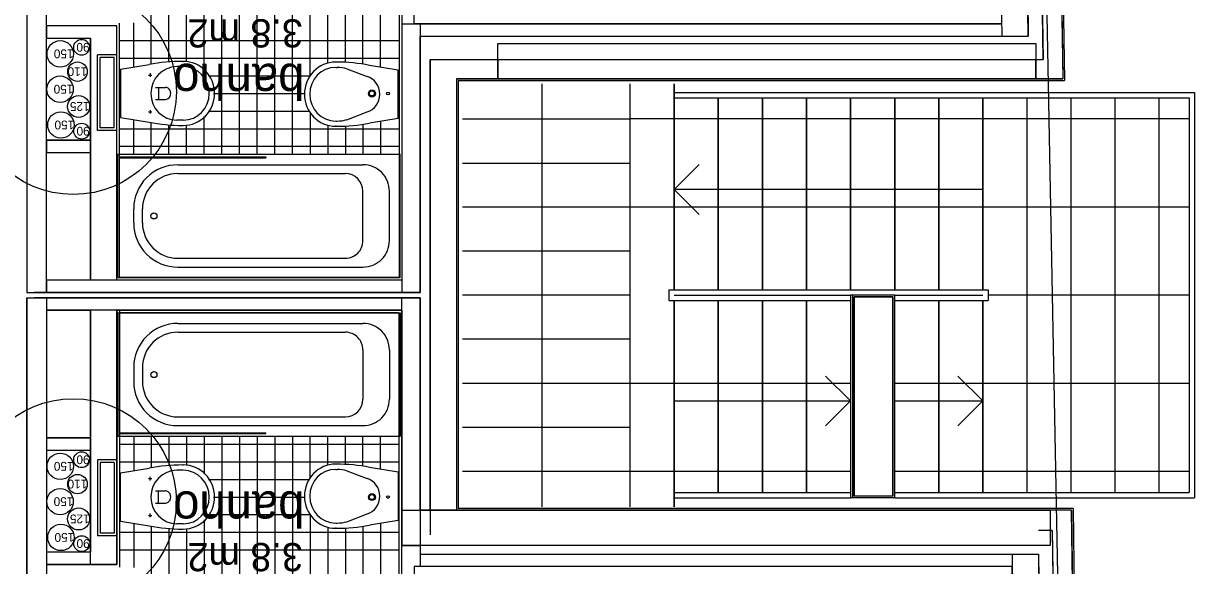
# Model space of a CAD drawing. Extents: x 1278 to 1356, y -253.7 to -224.
# Drawn here: x 1345.5 to 1352.14, y -240.96 to -237.88 of the extents above; entities that cross this region are included whole.
import ezdxf

# ---------------------------------------------------------------- set-up
doc = ezdxf.new("R2010")
doc.units = 0
for name, color, linetype in [('Level 1', 7, 'Continuous'), ('Level 10', 7, 'Continuous'), ('Level 11', 7, 'Continuous'), ('Level 2', 7, 'Continuous'), ('Level 36', 7, 'Continuous'), ('Level 41', 7, 'Continuous'), ('Level 60', 7, 'Continuous'), ('Level 65', 7, 'Continuous'), ('Level 66', 7, 'Continuous'), ('Level 67', 7, 'Continuous'), ('Level 69', 7, 'Continuous'), ('Level 70', 7, 'Continuous')]:
    doc.layers.add(name, color=color, linetype=linetype)

msp = doc.modelspace()

# ---------------------------------------------------------------- linework, layer by layer
at = {"layer": 'Level 1'}
for p, q in [((1351.0269, -236.264), (1351.0505, -237.954)), ((1351.1769, -236.2619), (1351.2005, -237.954)), ((1345.524, -236.7713), (1345.524, -239.409)), ((1347.6487, -237.829), (1347.6487, -239.409)), ((1347.6487, -237.884), (1351.0496, -237.884)), ((1347.719, -237.884), (1347.719, -237.829)), ((1347.754, -237.884), (1347.754, -239.409)), ((1346.034, -237.896), (1345.634, -237.896)), ((1346.034, -239.339), (1346.034, -237.896)), ((1345.884, -239.339), (1345.884, -237.966)), ((1347.754, -237.954), (1351.2005, -237.954)), ((1347.809, -238.0861), (1347.809, -240.784)), ((1347.809, -238.0861), (1351.2841, -238.0861)), ((1347.959, -238.1961), (1347.959, -240.644)), ((1347.959, -238.1961), (1351.3957, -238.1961)), ((1345.6348, -238.544), (1345.884, -238.544)), ((1345.6348, -238.614), (1345.884, -238.614)), ((1347.6487, -239.339), (1345.634, -239.339)), ((1345.524, -239.409), (1347.754, -239.409)), ((1347.754, -239.409), (1345.564, -239.409)), ((1347.644, -239.409), (1345.564, -239.409)), ((1345.524, -239.439), (1347.754, -239.439)), ((1345.524, -239.439), (1345.524, -246.584)), ((1347.754, -239.439), (1345.564, -239.439)), ((1347.644, -239.439), (1345.564, -239.439)), ((1345.634, -239.439), (1345.634, -246.584)), ((1347.6487, -241.019), (1347.6487, -239.439)), ((1347.754, -239.439), (1347.754, -240.964)), ((1350.4433, -239.424), (1350.1933, -239.424)), ((1350.1933, -239.424), (1350.1933, -240.574)), ((1350.2033, -239.424), (1350.2033, -240.574)), ((1350.2133, -239.434), (1350.2133, -240.564)), ((1350.4333, -239.434), (1350.2133, -239.434)), ((1350.4333, -240.564), (1350.4333, -239.434)), ((1350.4433, -240.574), (1350.4433, -239.424)), ((1347.6487, -239.509), (1345.634, -239.509)), ((1346.034, -239.509), (1346.034, -240.952)), ((1345.6348, -240.234), (1345.884, -240.234)), ((1345.6348, -240.304), (1345.884, -240.304)), ((1345.6348, -240.304), (1345.884, -240.304)), ((1350.4433, -240.574), (1350.1933, -240.574)), ((1350.4333, -240.564), (1350.2133, -240.564)), ((1351.4448, -240.644), (1347.959, -240.644)), ((1351.4448, -240.644), (1351.5324, -246.914)), ((1351.3364, -240.7593), (1351.4208, -246.804)), ((1345.884, -240.882), (1345.634, -240.882)), ((1347.754, -240.894), (1351.2583, -240.894)), ((1351.1083, -240.894), (1351.1877, -246.584)), ((1351.2583, -240.894), (1351.3398, -246.734))]:
    msp.add_line(p, q, dxfattribs=at)
at = {"layer": 'Level 10'}
for p, q in [((1346.229, -238.1127), (1346.229, -237.079)), ((1346.329, -238.0998), (1346.329, -237.079)), ((1346.429, -238.0988), (1346.429, -237.079)), ((1346.529, -238.1489), (1346.529, -237.079)), ((1346.629, -238.624), (1346.629, -237.079)), ((1346.729, -238.624), (1346.729, -237.079)), ((1346.829, -238.624), (1346.829, -237.079)), ((1346.929, -238.624), (1346.929, -237.079)), ((1347.029, -238.624), (1347.029, -237.079)), ((1347.129, -238.1791), (1347.129, -237.169)), ((1347.229, -238.1075), (1347.229, -237.169)), ((1347.329, -238.1028), (1347.329, -237.169)), ((1347.429, -238.1133), (1347.429, -237.169)), ((1347.529, -238.1303), (1347.529, -237.169)), ((1346.129, -238.1292), (1346.129, -237.879)), ((1346.049, -237.979), (1347.6337, -237.979)), ((1346.049, -238.079), (1347.6337, -238.079)), ((1346.5533, -238.179), (1347.1291, -238.179)), ((1346.5825, -238.279), (1347.0969, -238.279)), ((1348.4433, -238.224), (1348.4433, -240.624)), ((1348.9433, -240.624), (1348.9433, -238.224)), ((1349.1933, -239.394), (1349.1933, -238.224)), ((1349.4433, -239.394), (1349.4433, -238.304)), ((1349.6933, -239.394), (1349.6933, -238.304)), ((1349.9433, -239.394), (1349.9433, -238.304)), ((1350.1933, -239.394), (1350.1933, -238.304)), ((1350.4433, -239.394), (1350.4433, -238.304)), ((1350.6933, -239.394), (1350.6933, -238.304)), ((1350.9433, -239.394), (1350.9433, -238.304)), ((1351.1933, -240.544), (1351.1933, -238.304)), ((1351.4433, -240.544), (1351.4433, -238.304)), ((1351.6933, -240.544), (1351.6933, -238.304)), ((1351.9433, -240.544), (1351.9433, -238.304)), ((1346.529, -238.624), (1346.529, -238.4091)), ((1346.5533, -238.379), (1347.1232, -238.379)), ((1347.129, -238.388), (1347.129, -238.624)), ((1346.049, -238.479), (1347.6337, -238.479)), ((1346.129, -238.624), (1346.129, -238.4288)), ((1346.229, -238.624), (1346.229, -238.4452)), ((1346.329, -238.624), (1346.329, -238.4582)), ((1346.429, -238.624), (1346.429, -238.4592)), ((1347.229, -238.4596), (1347.229, -238.624)), ((1347.329, -238.4643), (1347.329, -238.624)), ((1347.429, -238.4538), (1347.429, -238.624)), ((1347.529, -238.4368), (1347.529, -238.624)), ((1347.9933, -238.424), (1348.9433, -238.424)), ((1352.1133, -238.424), (1348.9433, -238.424)), ((1346.049, -238.579), (1347.634, -238.579)), ((1347.9933, -238.674), (1348.9433, -238.674)), ((1348.9433, -238.924), (1347.9933, -238.924)), ((1352.1133, -238.924), (1348.9433, -238.924)), ((1348.9433, -239.174), (1347.9933, -239.174)), ((1348.9433, -239.424), (1347.9933, -239.424)), ((1349.1933, -240.624), (1349.1933, -239.454)), ((1349.4433, -240.544), (1349.4433, -239.454)), ((1349.6933, -240.544), (1349.6933, -239.454)), ((1349.9433, -240.544), (1349.9433, -239.454)), ((1350.6933, -240.544), (1350.6933, -239.454)), ((1350.9433, -240.544), (1350.9433, -239.454)), ((1352.1133, -239.424), (1350.9733, -239.424)), ((1348.9433, -239.674), (1347.9933, -239.674)), ((1348.9433, -239.924), (1347.9933, -239.924)), ((1350.1933, -239.924), (1348.9433, -239.924)), ((1352.1133, -239.924), (1350.4433, -239.924)), ((1348.9433, -240.174), (1347.9933, -240.174)), ((1346.049, -240.269), (1347.634, -240.269)), ((1346.129, -240.224), (1346.129, -240.4192)), ((1346.229, -240.224), (1346.229, -240.4027)), ((1346.329, -240.224), (1346.329, -240.3898)), ((1346.429, -240.224), (1346.429, -240.3888)), ((1346.529, -240.224), (1346.529, -240.4388)), ((1346.629, -240.224), (1346.629, -241.769)), ((1346.729, -240.224), (1346.729, -241.769)), ((1346.829, -240.224), (1346.829, -241.769)), ((1346.929, -240.224), (1346.929, -241.769)), ((1347.029, -240.224), (1347.029, -241.769)), ((1347.129, -240.4599), (1347.129, -240.224)), ((1347.229, -240.3884), (1347.229, -240.224)), ((1347.329, -240.3837), (1347.329, -240.224)), ((1347.429, -240.3942), (1347.429, -240.224)), ((1347.529, -240.4111), (1347.529, -240.224)), ((1346.049, -240.369), (1347.629, -240.369)), ((1346.5533, -240.469), (1347.1232, -240.469)), ((1348.9433, -240.424), (1347.9933, -240.424)), ((1350.1933, -240.424), (1348.9433, -240.424)), ((1352.1133, -240.424), (1350.4433, -240.424)), ((1346.5825, -240.569), (1347.0969, -240.569)), ((1346.5533, -240.669), (1347.1291, -240.669)), ((1347.129, -240.6689), (1347.129, -241.679)), ((1346.129, -240.7188), (1346.129, -240.969)), ((1346.229, -240.7352), (1346.229, -241.769)), ((1346.529, -240.6991), (1346.529, -241.769)), ((1347.429, -240.7346), (1347.429, -241.679)), ((1347.529, -240.7177), (1347.529, -241.679)), ((1346.049, -240.769), (1347.629, -240.769)), ((1346.329, -240.7481), (1346.329, -241.769)), ((1346.429, -240.7491), (1346.429, -241.769)), ((1347.229, -240.7404), (1347.229, -241.679)), ((1347.329, -240.7451), (1347.329, -241.679)), ((1346.049, -240.869), (1347.629, -240.869))]:
    msp.add_line(p, q, dxfattribs=at)
at = {"layer": 'Level 11'}
for p, q in [((1346.034, -238.0596), (1345.924, -238.0596)), ((1345.924, -238.4896), (1345.924, -238.0596)), ((1345.939, -238.4746), (1345.939, -238.0746)), ((1346.019, -238.0746), (1345.939, -238.0746)), ((1346.019, -238.4746), (1346.019, -238.0746)), ((1346.034, -238.4896), (1346.034, -238.0596)), ((1346.054, -238.1423), (1346.2161, -238.1157)), ((1346.054, -238.1423), (1346.054, -238.4157)), ((1346.41, -238.1271), (1346.374, -238.1271)), ((1346.4067, -238.0972), (1346.4103, -238.0971)), ((1347.2778, -238.1015), (1347.2741, -238.1015)), ((1347.2744, -238.1315), (1347.2825, -238.1315)), ((1347.3374, -238.1392), (1347.4521, -238.1828)), ((1347.6287, -238.1467), (1347.4666, -238.12)), ((1347.6287, -238.4205), (1347.6287, -238.1467)), ((1346.2122, -238.1746), (1346.2322, -238.1746)), ((1346.2222, -238.1646), (1346.2222, -238.1846)), ((1346.2521, -238.2446), (1346.3092, -238.2446)), ((1346.2698, -238.2446), (1346.2698, -238.3133)), ((1346.2521, -238.3133), (1346.3093, -238.3133)), ((1346.2122, -238.3833), (1346.2322, -238.3833)), ((1346.2222, -238.3733), (1346.2222, -238.3933)), ((1347.3374, -238.428), (1347.4521, -238.3843)), ((1346.019, -238.4746), (1345.939, -238.4746)), ((1346.054, -238.4157), (1346.2161, -238.4423)), ((1346.41, -238.4308), (1346.374, -238.4308)), ((1346.4067, -238.4608), (1346.4103, -238.4608)), ((1347.2778, -238.4656), (1347.2741, -238.4656)), ((1347.2744, -238.4356), (1347.2825, -238.4356)), ((1347.6287, -238.4205), (1347.4666, -238.4471)), ((1346.034, -238.4896), (1345.924, -238.4896)), ((1346.039, -239.324), (1346.039, -238.624)), ((1346.039, -238.624), (1347.639, -238.624)), ((1347.639, -239.324), (1347.639, -238.624)), ((1346.379, -238.684), (1347.429, -238.684)), ((1346.379, -238.734), (1347.329, -238.734)), ((1347.429, -239.114), (1347.429, -238.834)), ((1347.579, -239.114), (1347.579, -238.834)), ((1346.129, -239.014), (1346.129, -238.934)), ((1346.179, -239.014), (1346.179, -238.934)), ((1346.379, -239.214), (1347.329, -239.214)), ((1346.379, -239.264), (1347.429, -239.264)), ((1346.039, -239.324), (1347.639, -239.324)), ((1346.039, -239.524), (1347.639, -239.524)), ((1346.039, -239.524), (1346.039, -240.224)), ((1347.639, -239.524), (1347.639, -240.224)), ((1346.379, -239.584), (1347.429, -239.584)), ((1346.379, -239.634), (1347.329, -239.634)), ((1347.429, -239.734), (1347.429, -240.014)), ((1347.579, -239.734), (1347.579, -240.014)), ((1346.129, -239.834), (1346.129, -239.914)), ((1346.179, -239.834), (1346.179, -239.914)), ((1346.379, -240.114), (1347.329, -240.114)), ((1346.379, -240.164), (1347.429, -240.164)), ((1346.039, -240.224), (1347.639, -240.224)), ((1346.034, -240.3583), (1345.924, -240.3583)), ((1345.924, -240.3583), (1345.924, -240.7883)), ((1345.939, -240.3733), (1345.939, -240.7733)), ((1346.019, -240.3733), (1345.939, -240.3733)), ((1346.019, -240.3733), (1346.019, -240.7733)), ((1346.034, -240.3583), (1346.034, -240.7883)), ((1346.054, -240.4323), (1346.2161, -240.4057)), ((1346.4067, -240.3871), (1346.4103, -240.3871)), ((1347.2778, -240.3823), (1347.2741, -240.3823)), ((1347.6287, -240.4275), (1347.4666, -240.4009)), ((1346.054, -240.7056), (1346.054, -240.4323)), ((1346.2122, -240.4646), (1346.2322, -240.4646)), ((1346.2222, -240.4746), (1346.2222, -240.4546)), ((1346.41, -240.4171), (1346.374, -240.4171)), ((1347.2744, -240.4123), (1347.2825, -240.4123)), ((1347.3374, -240.42), (1347.4521, -240.4637)), ((1347.6287, -240.4275), (1347.6287, -240.7013)), ((1346.2521, -240.5346), (1346.3093, -240.5346)), ((1346.2698, -240.6033), (1346.2698, -240.5346)), ((1346.2521, -240.6033), (1346.3092, -240.6033)), ((1346.2222, -240.6833), (1346.2222, -240.6633)), ((1347.3374, -240.7088), (1347.4521, -240.6651)), ((1346.054, -240.7056), (1346.2161, -240.7323)), ((1346.2122, -240.6733), (1346.2322, -240.6733)), ((1346.41, -240.7208), (1346.374, -240.7208)), ((1347.2744, -240.7165), (1347.2825, -240.7165)), ((1347.6287, -240.7013), (1347.4666, -240.7279)), ((1346.034, -240.7883), (1345.924, -240.7883)), ((1346.019, -240.7733), (1345.939, -240.7733)), ((1346.4067, -240.7508), (1346.4103, -240.7508)), ((1347.2778, -240.7465), (1347.2741, -240.7465))]:
    msp.add_line(p, q, dxfattribs=at)
for centre, radius in [((1347.4798, -238.279), 0.02), ((1347.4798, -238.279), 0.0146), ((1347.5707, -238.279), 0.00766), ((1346.2435, -238.974), 0.0173), ((1346.2435, -239.874), 0.0173), ((1347.4798, -240.569), 0.02), ((1347.4798, -240.569), 0.0146), ((1347.5707, -240.569), 0.00766)]:
    msp.add_circle(centre, radius, dxfattribs=at)
for centre, radius, start, end in [((1347.2825, -238.3315), 0.2, 74.06814, 89.99835), ((1347.2825, -238.2356), 0.2, 269.99944, 285.93072), ((1346.379, -238.934), 0.25, 89.99999, 180.0001), ((1346.379, -238.934), 0.2, 89.99997, 180.00002), ((1347.329, -238.834), 0.1, 0.00014, 89.99987), ((1347.429, -238.834), 0.15, 359.9999, 90.00017), ((1346.379, -239.014), 0.25, 179.99986, 269.99993), ((1346.379, -239.014), 0.2, 179.99997, 270.00001), ((1347.329, -239.114), 0.1, 269.99997, 0.00005), ((1347.429, -239.114), 0.15, 269.99996, 359.99999), ((1346.379, -239.834), 0.25, 90.00007, 180.00014), ((1347.429, -239.734), 0.15, 0.00001, 90.00004), ((1346.379, -239.834), 0.2, 89.99999, 180.00003), ((1347.329, -239.734), 0.1, 359.99995, 90.00003), ((1346.379, -239.914), 0.25, 179.9999, 270.00001), ((1346.379, -239.914), 0.2, 179.99998, 270.00003), ((1347.329, -240.014), 0.1, 270.00013, 359.99986), ((1347.429, -240.014), 0.15, 269.99983, 0.0001), ((1347.2825, -240.6123), 0.2, 74.06928, 90.00056), ((1347.2825, -240.5165), 0.2, 270.00165, 285.93186)]:
    msp.add_arc(centre, radius, start, end, dxfattribs=at)
for centre, major_axis, ratio, start_param, end_param in [((1346.4067, -239.4969), (0, 1.3998), 0.839409, 6.283183, 6.446101), ((1346.374, -238.279), (0, -0.1518), 0.971435, 3.141595, 6.283182), ((1346.41, -238.279), (0, -0.1818), 0.976148, 0.000002, 3.141589), ((1346.41, -238.279), (0, -0.1518), 0.971435, 0.000002, 3.141589), ((1347.2744, -238.2835), (0, 0.1821), 0.974849, 0.000002, 3.141589), ((1347.2744, -238.2835), (0, 0.1521), 0.969887, 0.000002, 3.141589), ((1347.2778, -239.5017), (0, 1.4003), 0.831536, 6.120269, 6.283187), ((1347.4247, -238.2835), (0, 0.1048), 0.954554, 3.417437, 6.005125), ((1346.3091, -238.279), (0, -0.0343), 0.873689, 6.283163, 9.424786), ((1346.4067, -237.0606), (0, -1.4002), 0.839116, 6.120268, 6.283186), ((1347.2778, -237.0659), (0, -1.3997), 0.831849, 6.283183, 6.446102), ((1346.4067, -241.7873), (0, 1.4002), 0.839116, 6.283184, 6.446103), ((1346.41, -240.5689), (0, 0.1818), 0.976148, 3.141597, 6.283184), ((1347.2744, -240.5644), (0, -0.1821), 0.974849, 3.141596, 6.283183), ((1347.2778, -241.7821), (0, 1.3997), 0.831849, 6.120269, 6.283187), ((1346.374, -240.5689), (0, 0.1518), 0.971435, 0.000003, 3.14159), ((1346.41, -240.5689), (0, 0.1518), 0.971435, 3.141597, 6.283184), ((1347.2744, -240.5644), (0, -0.1521), 0.969887, 3.141596, 6.283183), ((1347.4247, -240.5644), (0, -0.1048), 0.954554, 0.27806, 2.865748), ((1346.3091, -240.5689), (0, 0.0343), 0.873689, 3.141584, 6.283207), ((1346.4067, -239.351), (0, -1.3998), 0.839409, 6.120269, 6.283188), ((1347.2778, -239.3462), (0, -1.4003), 0.831536, 6.283183, 6.446102)]:
    msp.add_ellipse(centre, major_axis=major_axis, ratio=ratio, start_param=start_param, end_param=end_param, dxfattribs=at)
at = {"layer": 'Level 2'}
for p, q in [((1349.1933, -238.224), (1349.1933, -239.394)), ((1349.1933, -238.274), (1352.1433, -238.274)), ((1352.1433, -238.274), (1352.1433, -240.574)), ((1349.1933, -238.304), (1352.1133, -238.304)), ((1349.4433, -238.304), (1349.4433, -239.394)), ((1349.6933, -238.304), (1349.6933, -239.394)), ((1349.9433, -238.304), (1349.9433, -239.394)), ((1350.1933, -238.304), (1350.1933, -239.394)), ((1350.4433, -238.304), (1350.4433, -239.394)), ((1350.6933, -238.304), (1350.6933, -239.394)), ((1350.9433, -238.304), (1350.9433, -239.394)), ((1352.1133, -238.304), (1352.1133, -240.544)), ((1349.3347, -238.6826), (1349.1933, -238.824)), ((1350.9433, -238.824), (1349.1933, -238.824)), ((1349.3347, -238.9654), (1349.1933, -238.824)), ((1349.1633, -239.394), (1350.9733, -239.394)), ((1349.1633, -239.394), (1349.1633, -239.454)), ((1350.9733, -239.394), (1350.9733, -239.454)), ((1349.1633, -239.454), (1350.1933, -239.454)), ((1349.1933, -239.424), (1350.1933, -239.424)), ((1349.1933, -239.454), (1349.1933, -240.574)), ((1349.4433, -239.454), (1349.4433, -240.544)), ((1349.6933, -239.454), (1349.6933, -240.544)), ((1349.9433, -239.454), (1349.9433, -240.544)), ((1350.4433, -239.424), (1350.9433, -239.424)), ((1350.4433, -239.454), (1350.9733, -239.454)), ((1350.6933, -239.454), (1350.6933, -240.544)), ((1350.9433, -239.454), (1350.9433, -240.544)), ((1350.0519, -239.8826), (1350.1933, -240.024)), ((1350.8019, -239.8826), (1350.9433, -240.024)), ((1349.1933, -240.024), (1350.1933, -240.024)), ((1350.0519, -240.1654), (1350.1933, -240.024)), ((1350.4433, -240.024), (1350.9433, -240.024)), ((1350.8019, -240.1654), (1350.9433, -240.024)), ((1349.1933, -240.544), (1350.1933, -240.544)), ((1349.1933, -240.574), (1350.1933, -240.574)), ((1349.1933, -240.574), (1349.1933, -240.624)), ((1350.4433, -240.544), (1352.1133, -240.544)), ((1350.4433, -240.574), (1352.1433, -240.574))]:
    msp.add_line(p, q, dxfattribs=at)
at = {"layer": 'Level 36'}
for p, q in [((1346.049, -238.639), (1346.8791, -238.639)), ((1346.049, -238.644), (1346.8791, -238.644)), ((1346.8791, -238.639), (1346.8791, -238.644)), ((1346.049, -240.204), (1346.8791, -240.204)), ((1346.8791, -240.209), (1346.8791, -240.204)), ((1346.049, -240.209), (1346.8791, -240.209))]:
    msp.add_line(p, q, dxfattribs=at)
at = {"layer": 'Level 41'}
for centre, radius in [((1345.713, -238.0546), 0.075), ((1345.834, -238.0173), 0.045), ((1345.8106, -238.1555), 0.055), ((1345.7119, -238.2551), 0.075), ((1345.8167, -238.3532), 0.0625), ((1345.7168, -238.4581), 0.075), ((1345.8346, -238.4932), 0.045), ((1345.713, -240.3946), 0.075), ((1345.834, -240.3573), 0.045), ((1345.8106, -240.4955), 0.055), ((1345.7119, -240.5951), 0.075), ((1345.8167, -240.6932), 0.0625), ((1345.7168, -240.7981), 0.075), ((1345.8346, -240.8332), 0.045)]:
    msp.add_circle(centre, radius, dxfattribs=at)
at = {"layer": 'Level 65'}
for p, q in [((1351.3157, -231.924), (1351.4058, -238.2061)), ((1346.049, -239.324), (1346.049, -237.881)), ((1347.6337, -237.829), (1347.6337, -239.324)), ((1347.969, -238.2061), (1347.969, -240.634)), ((1347.969, -238.2061), (1351.4058, -238.2061)), ((1347.6337, -239.324), (1346.049, -239.324)), ((1346.049, -239.509), (1346.049, -240.967)), ((1347.629, -239.524), (1346.049, -239.524)), ((1347.6337, -241.019), (1347.6337, -239.524)), ((1351.4547, -240.634), (1347.969, -240.634)), ((1351.4547, -240.634), (1351.5425, -246.924))]:
    msp.add_line(p, q, dxfattribs=at)
at = {"layer": 'Level 66'}
for p, q in [((1351.3059, -231.934), (1351.3957, -238.1961)), ((1351.1974, -232.044), (1351.2841, -238.0861)), ((1345.634, -239.409), (1345.634, -232.264)), ((1345.884, -240.952), (1345.884, -239.509)), ((1347.809, -240.644), (1347.754, -240.644)), ((1351.3364, -240.7593), (1351.2593, -240.7593)), ((1346.034, -240.952), (1345.634, -240.952))]:
    msp.add_line(p, q, dxfattribs=at)
for points in [[(1351.2438, -238.1963), (1348.1927, -238.1963), (1348.1927, -237.9963), (1351.2438, -237.9963)], [(1351.3241, -240.844), (1347.6511, -240.844), (1347.6511, -240.644), (1351.3241, -240.644)]]:
    msp.add_lwpolyline(points, close=True, dxfattribs=at)
at = {"layer": 'Level 67'}
for points in [[(1351.3957, -238.1961), (1351.2438, -238.1961), (1351.2438, -238.0861), (1351.2841, -238.0861), (1351.1974, -232.044), (1350.874, -232.044), (1350.874, -232.114), (1350.9719, -232.114), (1350.9711, -232.264), (1350.804, -232.264), (1350.804, -231.934), (1351.3059, -231.934), (1351.3957, -238.1961)], [(1345.634, -237.896), (1345.634, -237.966), (1345.884, -237.966), (1345.884, -239.339), (1345.634, -239.339), (1345.634, -239.409), (1347.754, -239.409), (1347.754, -238.034), (1347.754, -237.954), (1351.2005, -237.954), (1351.1769, -236.2619), (1351.0269, -236.264), (1351.0496, -237.884), (1347.719, -237.884), (1347.719, -237.829), (1347.6487, -237.829), (1347.6487, -239.339), (1346.034, -239.339), (1346.034, -237.896)], [(1345.634, -236.7713), (1345.524, -236.7713), (1345.524, -239.409), (1345.634, -239.409), (1345.634, -236.7713)], [(1347.9584, -240.644), (1347.809, -240.644), (1347.809, -238.0861), (1348.1927, -238.0861), (1348.1927, -238.1961), (1347.959, -238.1961), (1347.959, -240.644)], [(1345.884, -238.544), (1345.634, -238.544), (1345.634, -238.614), (1345.884, -238.614)], [(1345.634, -242.1713), (1345.524, -242.1713), (1345.524, -239.439), (1345.634, -239.439), (1345.634, -242.1713)], [(1345.634, -240.882), (1345.634, -240.952), (1346.034, -240.952), (1346.034, -239.509), (1347.6487, -239.509), (1347.6487, -240.644), (1347.754, -240.644), (1347.754, -239.439), (1345.634, -239.439), (1345.634, -239.509), (1345.884, -239.509), (1345.884, -240.882), (1345.634, -240.882)], [(1350.4333, -239.434), (1350.4333, -240.564), (1350.2133, -240.564), (1350.2133, -239.434)], [(1345.884, -240.234), (1345.634, -240.234), (1345.634, -240.304), (1345.884, -240.304)], [(1351.1877, -246.584), (1350.804, -246.584), (1350.8054, -246.601), (1350.804, -246.914), (1351.5324, -246.914), (1351.4448, -240.644), (1351.3241, -240.644), (1351.3241, -240.7593), (1351.3364, -240.7593), (1351.4208, -246.804), (1350.874, -246.804), (1350.874, -246.734), (1351.1891, -246.734)], [(1351.2583, -240.894), (1351.2819, -242.5869), (1351.1312, -242.589), (1351.1093, -240.964), (1347.719, -240.964), (1347.719, -241.019), (1347.6487, -241.019), (1347.6487, -240.844), (1347.754, -240.844), (1347.754, -240.894)]]:
    msp.add_lwpolyline(points, close=True, dxfattribs=at)
at = {"layer": 'Level 69'}
for centre in [(1345.7869, -238.2684), (1345.7869, -240.5951)]:
    msp.add_circle(centre, 0.5842, dxfattribs=at)
at = {"layer": 'Level 70'}
msp.add_line((1351.1483, -229.6198), (1351.553, -250.7923), dxfattribs=at)

# ---------------------------------------------------------------- texts
at = {"layer": 'Level 41'}
for s, p in [('90', (1345.879, -237.9923)), ('150', (1345.788, -238.0296)), ('110', (1345.8656, -238.1305)), ('150', (1345.7869, -238.2301)), ('125', (1345.8792, -238.3282)), ('150', (1345.7918, -238.4331)), ('90', (1345.8796, -238.4682)), ('90', (1345.879, -240.3323)), ('150', (1345.788, -240.3696)), ('110', (1345.8656, -240.4705)), ('150', (1345.7869, -240.5701)), ('125', (1345.8792, -240.6682)), ('150', (1345.7918, -240.7731)), ('90', (1345.8796, -240.8082))]:
    msp.add_text(s, height=0.05, rotation=180, dxfattribs=at).set_placement(p)
at = {"layer": 'Level 60'}
for s, height, p in [('3.8 m2', 0.16, (1347.0883, -237.8582)), ('banho', 0.2, (1347.0968, -238.111)), ('banho', 0.2, (1347.0968, -240.537)), ('3.8 m2', 0.16, (1347.0883, -240.8297))]:
    msp.add_text(s, height=height, rotation=180, dxfattribs=at).set_placement(p)

doc.saveas('drawing.dxf')
